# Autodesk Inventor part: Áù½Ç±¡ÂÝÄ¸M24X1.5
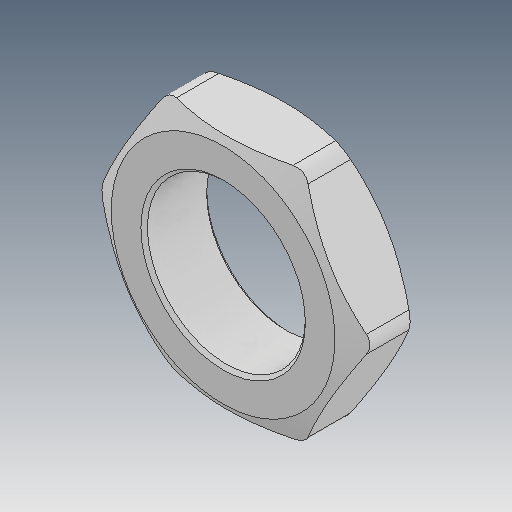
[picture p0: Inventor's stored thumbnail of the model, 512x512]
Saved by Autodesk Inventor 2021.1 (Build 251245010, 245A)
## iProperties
Created: 2019-04
Part Number: Áù½Ç±¡ÂÝÄ¸M24X1.5
Material: Ogólny
Document SubType Name: Modeling
Designer: user
Density: 1 g/cm^3
Appearance: Domyślna
Author: user
Revision Number: ÈÎºÎ
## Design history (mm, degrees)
feature "µ¹½Ç2"
node "Bryła1"
